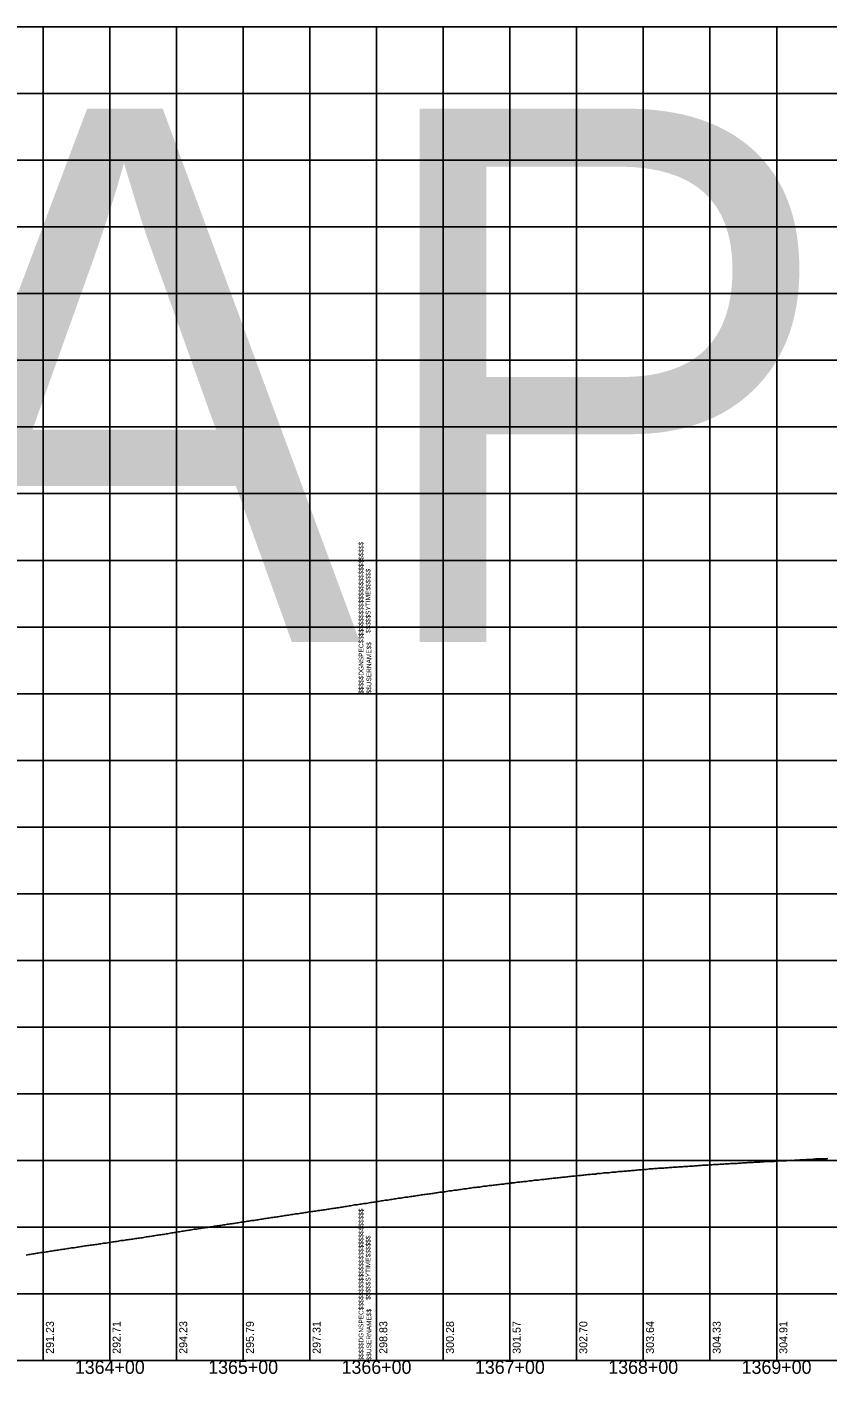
# Model space of a CAD drawing. Extents: x -90830 to 2015517, y -20856 to 836331.
# Drawn here: x 15761 to 16361, y 20053 to 21063 of the extents above; entities that cross this region are included whole.
import ezdxf

# ---------------------------------------------------------------- set-up
doc = ezdxf.new("R2010")
doc.units = 0
for name, color, linetype in [('Level 1', 7, 'Continuous'), ('RD_DDB_Profile_EX', 7, 'Continuous'), ('RD_DDB_StaTX', 7, 'Continuous'), ('RD_DDB_StripGrade', 7, 'Continuous'), ('RD_GPK_Profile_Cell', 7, 'Continuous')]:
    doc.layers.add(name, color=color, linetype=linetype)

msp = doc.modelspace()

# ---------------------------------------------------------------- linework, layer by layer
at = {"layer": 'Level 1'}
for p, q in [((14423.5, 21062.9), (16023.5, 21062.9)), ((15773.5, 21062.9), (15773.5, 20562.9)), ((15823.5, 21062.9), (15823.5, 20562.9)), ((15873.5, 21062.9), (15873.5, 20562.9)), ((15923.5, 21062.9), (15923.5, 20562.9)), ((15973.5, 21062.9), (15973.5, 20562.9)), ((16023.5, 21062.9), (16023.5, 20562.9)), ((16023.5, 21062.9), (16023.5, 20562.9)), ((16023.5, 21062.9), (17623.5, 21062.9)), ((16023.5, 21062.9), (16023.5, 20562.9)), ((16073.5, 21062.9), (16073.5, 20562.9)), ((16123.5, 21062.9), (16123.5, 20562.9)), ((16173.5, 21062.9), (16173.5, 20562.9)), ((16223.5, 21062.9), (16223.5, 20562.9)), ((16273.5, 21062.9), (16273.5, 20562.9)), ((16323.5, 21062.9), (16323.5, 20562.9)), ((14423.5, 21012.9), (16023.5, 21012.9)), ((16023.5, 21012.9), (17623.5, 21012.9)), ((14423.5, 20962.9), (16023.5, 20962.9)), ((16023.5, 20962.9), (17623.5, 20962.9)), ((14423.5, 20912.9), (16023.5, 20912.9)), ((16023.5, 20912.9), (17623.5, 20912.9)), ((14423.5, 20862.9), (16023.5, 20862.9)), ((16023.5, 20862.9), (17623.5, 20862.9)), ((14423.5, 20812.9), (16023.5, 20812.9)), ((16023.5, 20812.9), (17623.5, 20812.9)), ((14423.5, 20762.9), (16023.5, 20762.9)), ((16023.5, 20762.9), (17623.5, 20762.9)), ((14423.5, 20712.9), (16023.5, 20712.9)), ((16023.5, 20712.9), (17623.5, 20712.9)), ((14423.5, 20662.9), (16023.5, 20662.9)), ((16023.5, 20662.9), (17623.5, 20662.9)), ((14423.5, 20612.9), (16023.5, 20612.9)), ((16023.5, 20612.9), (17623.5, 20612.9)), ((14423.5, 20562.9), (16023.5, 20562.9)), ((14423.5, 20562.9), (16023.5, 20562.9)), ((15773.5, 20562.9), (15773.5, 20062.9)), ((15823.5, 20562.9), (15823.5, 20062.9)), ((15873.5, 20562.9), (15873.5, 20062.9)), ((15923.5, 20562.9), (15923.5, 20062.9)), ((15973.5, 20562.9), (15973.5, 20062.9)), ((16023.5, 20562.9), (17623.5, 20562.9)), ((16023.5, 20562.9), (16023.5, 20062.9)), ((16023.5, 20562.9), (16023.5, 20062.9)), ((16023.5, 20562.9), (17623.5, 20562.9)), ((16023.5, 20562.9), (16023.5, 20062.9)), ((16073.5, 20562.9), (16073.5, 20062.9)), ((16123.5, 20562.9), (16123.5, 20062.9)), ((16173.5, 20562.9), (16173.5, 20062.9)), ((16223.5, 20562.9), (16223.5, 20062.9)), ((16273.5, 20562.9), (16273.5, 20062.9)), ((16323.5, 20562.9), (16323.5, 20062.9)), ((14423.5, 20512.9), (16023.5, 20512.9)), ((16023.5, 20512.9), (17623.5, 20512.9)), ((14423.5, 20462.9), (16023.5, 20462.9)), ((16023.5, 20462.9), (17623.5, 20462.9)), ((14423.5, 20412.9), (16023.5, 20412.9)), ((16023.5, 20412.9), (17623.5, 20412.9)), ((14423.5, 20362.9), (16023.5, 20362.9)), ((16023.5, 20362.9), (17623.5, 20362.9)), ((14423.5, 20312.9), (16023.5, 20312.9)), ((16023.5, 20312.9), (17623.5, 20312.9)), ((14423.5, 20262.9), (16023.5, 20262.9)), ((16023.5, 20262.9), (17623.5, 20262.9)), ((14423.5, 20212.9), (16023.5, 20212.9)), ((16023.5, 20212.9), (17623.5, 20212.9)), ((14423.5, 20162.9), (16023.5, 20162.9)), ((16023.5, 20162.9), (17623.5, 20162.9)), ((14423.5, 20112.9), (16023.5, 20112.9)), ((16023.5, 20112.9), (17623.5, 20112.9)), ((14423.5, 20062.9), (16023.5, 20062.9)), ((16023.5, 20062.9), (17623.5, 20062.9))]:
    msp.add_line(p, q, dxfattribs=at)
at = {"layer": 'RD_DDB_Profile_EX'}
for points in [[(16236.8, 20207.1), (16237.8, 20207.2), (16238.8, 20207.2), (16239.8, 20207.3), (16240.8, 20207.4), (16241.8, 20207.4), (16242.8, 20207.6), (16243.8, 20207.5), (16244.8, 20207.7), (16245.8, 20207.8), (16246.8, 20207.8), (16247.8, 20207.9), (16248.8, 20207.9), (16249.8, 20208), (16250.8, 20208.1), (16251.8, 20208.1), (16252.8, 20208.2), (16253.8, 20208.3), (16254.8, 20208.3), (16255.8, 20208.4), (16256.8, 20208.4), (16257.8, 20208.5), (16258.8, 20208.6), (16259.8, 20208.7), (16260.8, 20208.7), (16261.8, 20208.8), (16262.8, 20208.9), (16263.8, 20208.9), (16264.8, 20209), (16265.8, 20209.2), (16266.8, 20209.2), (16267.8, 20209.3), (16268.8, 20209.3), (16269.8, 20209.3), (16270.8, 20209.4), (16271.8, 20209.4), (16272.8, 20209.5), (16273.8, 20209.5), (16274.8, 20209.7), (16275.8, 20209.8), (16276.8, 20209.8), (16277.8, 20209.8), (16278.8, 20209.9), (16279.8, 20209.9), (16280.8, 20210), (16281.8, 20210.1), (16282.8, 20210.1), (16283.8, 20210.1), (16284.8, 20210.3), (16285.8, 20210.3), (16286.8, 20210.3), (16287.8, 20210.4), (16288.8, 20210.5), (16289.8, 20210.6), (16290.8, 20210.6), (16291.8, 20210.7), (16292.8, 20210.7), (16293.8, 20210.7), (16294.8, 20210.8), (16295.8, 20210.9), (16296.8, 20210.9), (16297.8, 20211), (16298.8, 20211.1), (16299.8, 20211.1), (16300.8, 20211.2), (16301.8, 20211.3), (16302.8, 20211.4), (16303.8, 20211.4), (16304.8, 20211.4), (16305.8, 20211.4), (16306.8, 20211.5), (16307.8, 20211.5), (16308.8, 20211.6), (16309.8, 20211.7), (16310.8, 20211.7), (16311.8, 20211.8), (16312.8, 20211.8), (16313.8, 20211.9), (16314.8, 20212), (16315.8, 20212), (16316.8, 20212.1), (16317.8, 20212.2), (16318.8, 20212.2), (16319.8, 20212.2), (16320.8, 20212.2), (16321.8, 20212.2), (16322.8, 20212.3), (16323.8, 20212.5), (16324.8, 20212.5), (16325.8, 20212.5), (16326.8, 20212.6), (16327.8, 20212.6), (16328.8, 20212.6), (16329.8, 20212.7), (16330.8, 20212.7), (16331.8, 20212.9), (16332.8, 20212.9), (16333.8, 20212.9), (16334.8, 20213), (16335.8, 20212.9), (16336.8, 20213)], [(16336.8, 20213), (16337.8, 20213), (16338.8, 20213.1), (16339.8, 20213.2), (16340.8, 20213.3), (16341.8, 20213.4), (16342.8, 20213.4), (16343.8, 20213.4), (16344.8, 20213.4), (16345.8, 20213.5), (16346.8, 20213.6), (16347.8, 20213.6), (16348.8, 20213.6), (16349.8, 20213.7), (16350.8, 20213.8), (16351.8, 20213.8), (16352.8, 20214), (16353.8, 20214), (16354.8, 20214), (16355.8, 20214), (16356.8, 20214), (16357.8, 20214), (16358.8, 20214), (16359.8, 20214.1), (16360.8, 20214.2), (16361.8, 20214.3)], [(16136.8, 20197.4), (16137.8, 20197.5), (16138.8, 20197.6), (16139.8, 20197.7), (16140.8, 20197.9), (16141.8, 20198), (16142.8, 20198.1), (16143.8, 20198.2), (16144.8, 20198.2), (16145.8, 20198.3), (16146.8, 20198.5), (16147.8, 20198.6), (16148.8, 20198.7), (16149.8, 20198.8), (16150.8, 20198.9), (16151.8, 20199), (16152.8, 20199.2), (16153.8, 20199.3), (16154.8, 20199.4), (16155.8, 20199.5), (16156.8, 20199.6), (16157.8, 20199.7), (16158.8, 20199.8), (16159.8, 20199.9), (16160.8, 20200), (16161.8, 20200.2), (16162.8, 20200.3), (16163.8, 20200.3), (16164.8, 20200.4), (16165.8, 20200.6), (16166.8, 20200.7), (16167.8, 20200.9), (16168.8, 20200.9), (16169.8, 20201), (16170.8, 20201.1), (16171.8, 20201.2), (16172.8, 20201.3), (16173.8, 20201.4), (16174.8, 20201.6), (16175.8, 20201.7), (16176.8, 20201.7), (16177.8, 20201.8), (16178.8, 20201.9), (16179.8, 20202), (16180.8, 20202.1), (16181.8, 20202.3), (16182.8, 20202.4), (16183.8, 20202.4), (16184.8, 20202.5), (16185.8, 20202.6), (16186.8, 20202.7), (16187.8, 20202.7), (16188.8, 20203), (16189.8, 20203), (16190.8, 20203.2), (16191.8, 20203.2), (16192.8, 20203.3), (16193.8, 20203.5), (16194.8, 20203.6), (16195.8, 20203.6), (16196.8, 20203.7), (16197.8, 20203.7), (16198.8, 20203.8), (16199.8, 20204), (16200.8, 20204.1), (16201.8, 20204.2), (16202.8, 20204.2), (16203.8, 20204.4), (16204.8, 20204.5), (16205.8, 20204.6), (16206.8, 20204.6), (16207.8, 20204.7), (16208.8, 20204.8), (16209.8, 20204.8), (16210.8, 20204.9), (16211.8, 20205.1), (16212.8, 20205.2), (16213.8, 20205.2), (16214.8, 20205.4), (16215.8, 20205.4), (16216.8, 20205.4), (16217.8, 20205.6), (16218.8, 20205.7), (16219.8, 20205.8), (16220.8, 20205.9), (16221.8, 20205.9), (16222.8, 20206), (16223.8, 20206.1), (16224.8, 20206.2), (16225.8, 20206.2), (16226.8, 20206.3), (16227.8, 20206.5), (16228.8, 20206.5), (16229.8, 20206.6), (16230.8, 20206.6), (16231.8, 20206.8), (16232.8, 20206.8), (16233.8, 20206.9), (16234.8, 20207), (16235.8, 20207.1), (16236.8, 20207.1)], [(16036.8, 20184), (16037.8, 20184.1), (16038.8, 20184.3), (16039.8, 20184.5), (16040.8, 20184.6), (16041.8, 20184.7), (16042.8, 20184.9), (16043.8, 20185.1), (16044.8, 20185.3), (16045.8, 20185.3), (16046.8, 20185.4), (16047.8, 20185.6), (16048.8, 20185.8), (16049.8, 20185.9), (16050.8, 20186.1), (16051.8, 20186.2), (16052.8, 20186.4), (16053.8, 20186.5), (16054.8, 20186.7), (16055.8, 20186.8), (16056.8, 20187), (16057.8, 20187.2), (16058.8, 20187.3), (16059.8, 20187.4), (16060.8, 20187.5), (16061.8, 20187.6), (16062.8, 20187.8), (16063.8, 20187.9), (16064.8, 20188.1), (16065.8, 20188.2), (16066.8, 20188.4), (16067.8, 20188.5), (16068.8, 20188.7), (16069.8, 20188.9), (16070.8, 20189), (16071.8, 20189.1), (16072.8, 20189.2), (16073.8, 20189.3), (16074.8, 20189.4), (16075.8, 20189.7), (16076.8, 20189.8), (16077.8, 20190), (16078.8, 20190.1), (16079.8, 20190.1), (16080.8, 20190.4), (16081.8, 20190.5), (16082.8, 20190.6), (16083.8, 20190.6), (16084.8, 20190.9), (16085.8, 20191.1), (16086.8, 20191.2), (16087.8, 20191.4), (16088.8, 20191.6), (16089.8, 20191.7), (16090.8, 20191.7), (16091.8, 20191.8), (16092.8, 20192.1), (16093.8, 20192.2), (16094.8, 20192.3), (16095.8, 20192.5), (16096.8, 20192.6), (16097.8, 20192.7), (16098.8, 20192.9), (16099.8, 20192.9), (16100.8, 20192.9), (16101.8, 20193.2), (16102.8, 20193.4), (16103.8, 20193.5), (16104.8, 20193.6), (16105.8, 20193.7), (16106.8, 20193.8), (16107.8, 20194), (16108.8, 20194.1), (16109.8, 20194.2), (16110.8, 20194.3), (16111.8, 20194.4), (16112.8, 20194.6), (16113.8, 20194.7), (16114.8, 20194.8), (16115.8, 20194.9), (16116.8, 20195), (16117.8, 20195), (16118.8, 20195.1), (16119.8, 20195.4), (16120.8, 20195.5), (16121.8, 20195.5), (16122.8, 20195.6), (16123.8, 20195.7), (16124.8, 20196), (16125.8, 20196), (16126.8, 20196.1), (16127.8, 20196.3), (16128.8, 20196.5), (16129.8, 20196.5), (16130.8, 20196.5), (16131.8, 20196.8), (16132.8, 20196.9), (16133.8, 20197), (16134.8, 20197.1), (16135.8, 20197.2), (16136.8, 20197.4)], [(15936.8, 20168.8), (15937.8, 20169), (15938.8, 20169.1), (15939.8, 20169.3), (15940.8, 20169.5), (15941.8, 20169.6), (15942.8, 20169.7), (15943.8, 20169.9), (15944.8, 20170.1), (15945.8, 20170.2), (15946.8, 20170.3), (15947.8, 20170.5), (15948.8, 20170.6), (15949.8, 20170.7), (15950.8, 20171), (15951.8, 20171.2), (15952.8, 20171.2), (15953.8, 20171.4), (15954.8, 20171.6), (15955.8, 20171.7), (15956.8, 20171.9), (15957.8, 20172), (15958.8, 20172.2), (15959.8, 20172.3), (15960.8, 20172.5), (15961.8, 20172.7), (15962.8, 20172.8), (15963.8, 20172.9), (15964.8, 20173), (15965.8, 20173.2), (15966.8, 20173.3), (15967.8, 20173.5), (15968.8, 20173.6), (15969.8, 20173.8), (15970.8, 20174), (15971.8, 20174.1), (15972.8, 20174.3), (15973.8, 20174.5), (15974.8, 20174.6), (15975.8, 20174.7), (15976.8, 20174.9), (15977.8, 20175), (15978.8, 20175.2), (15979.8, 20175.4), (15980.8, 20175.4), (15981.8, 20175.6), (15982.8, 20175.7), (15983.8, 20175.9), (15984.8, 20176), (15985.8, 20176.2), (15986.8, 20176.3), (15987.8, 20176.5), (15988.8, 20176.6), (15989.8, 20176.8), (15990.8, 20176.9), (15991.8, 20177.1), (15992.8, 20177.2), (15993.8, 20177.4), (15994.8, 20177.5), (15995.8, 20177.7), (15996.8, 20177.9), (15997.8, 20178), (15998.8, 20178.2), (15999.8, 20178.3), (16000.8, 20178.5), (16001.8, 20178.6), (16002.8, 20178.8), (16003.8, 20178.9), (16004.8, 20179.1), (16005.8, 20179.3), (16006.8, 20179.5), (16007.8, 20179.6), (16008.8, 20179.7), (16009.8, 20179.9), (16010.8, 20180.1), (16011.8, 20180.2), (16012.8, 20180.3), (16013.8, 20180.5), (16014.8, 20180.7), (16015.8, 20180.7), (16016.8, 20180.9), (16017.8, 20181.1), (16018.8, 20181.3), (16019.8, 20181.4), (16020.8, 20181.5), (16021.8, 20181.6), (16022.8, 20181.9), (16023.8, 20182.1), (16024.8, 20182.2), (16025.8, 20182.3), (16026.8, 20182.5), (16027.8, 20182.6), (16028.8, 20182.8), (16029.8, 20183), (16030.8, 20183.1), (16031.8, 20183.1), (16032.8, 20183.3), (16033.8, 20183.5), (16034.8, 20183.7), (16035.8, 20183.8), (16036.8, 20184)], [(15836.8, 20153.5), (15837.8, 20153.6), (15838.8, 20153.7), (15839.8, 20153.8), (15840.8, 20154), (15841.8, 20154.2), (15842.8, 20154.3), (15843.8, 20154.5), (15844.8, 20154.6), (15845.8, 20154.7), (15846.8, 20154.9), (15847.8, 20155), (15848.8, 20155.1), (15849.8, 20155.4), (15850.8, 20155.6), (15851.8, 20155.7), (15852.8, 20155.9), (15853.8, 20156), (15854.8, 20156.1), (15855.8, 20156.3), (15856.8, 20156.4), (15857.8, 20156.6), (15858.8, 20156.8), (15859.8, 20157), (15860.8, 20157.1), (15861.8, 20157.2), (15862.8, 20157.4), (15863.8, 20157.5), (15864.8, 20157.7), (15865.8, 20157.9), (15866.8, 20158), (15867.8, 20158.2), (15868.8, 20158.4), (15869.8, 20158.6), (15870.8, 20158.7), (15871.8, 20158.8), (15872.8, 20158.9), (15873.8, 20159.1), (15874.8, 20159.3), (15875.8, 20159.5), (15876.8, 20159.7), (15877.8, 20159.9), (15878.8, 20160), (15879.8, 20160.1), (15880.8, 20160.3), (15881.8, 20160.4), (15882.8, 20160.6), (15883.8, 20160.7), (15884.8, 20160.9), (15885.8, 20161.1), (15886.8, 20161.3), (15887.8, 20161.4), (15888.8, 20161.5), (15889.8, 20161.7), (15890.8, 20161.8), (15891.8, 20162), (15892.8, 20162.2), (15893.8, 20162.3), (15894.8, 20162.5), (15895.8, 20162.6), (15896.8, 20162.6), (15897.8, 20162.9), (15898.8, 20163.1), (15899.8, 20163.2), (15900.8, 20163.4), (15901.8, 20163.6), (15902.8, 20163.7), (15903.8, 20163.8), (15904.8, 20164), (15905.8, 20164.1), (15906.8, 20164.2), (15907.8, 20164.5), (15908.8, 20164.6), (15909.8, 20164.7), (15910.8, 20164.9), (15911.8, 20165.1), (15912.8, 20165.2), (15913.8, 20165.4), (15914.8, 20165.5), (15915.8, 20165.7), (15916.8, 20165.7), (15917.8, 20165.9), (15918.8, 20166.1), (15919.8, 20166.2), (15920.8, 20166.4), (15921.8, 20166.6), (15922.8, 20166.7), (15923.8, 20166.9), (15924.8, 20167), (15925.8, 20167.1), (15926.8, 20167.3), (15927.8, 20167.5), (15928.8, 20167.6), (15929.8, 20167.8), (15930.8, 20167.8), (15931.8, 20168), (15932.8, 20168.2), (15933.8, 20168.3), (15934.8, 20168.5), (15935.8, 20168.7), (15936.8, 20168.8)], [(15760.8, 20142), (15761.8, 20142.2), (15762.8, 20142.4), (15763.8, 20142.5), (15764.8, 20142.7), (15765.8, 20142.8), (15766.8, 20143), (15767.8, 20143.1), (15768.8, 20143.3), (15769.8, 20143.4), (15770.8, 20143.6), (15771.8, 20143.8), (15772.8, 20143.9), (15773.8, 20144), (15774.8, 20144.2), (15775.8, 20144.3), (15776.8, 20144.5), (15777.8, 20144.7), (15778.8, 20144.8), (15779.8, 20145), (15780.8, 20145.1), (15781.8, 20145.3), (15782.8, 20145.4), (15783.8, 20145.6), (15784.8, 20145.7), (15785.8, 20145.9), (15786.8, 20146.1), (15787.8, 20146.2), (15788.8, 20146.3), (15789.8, 20146.5), (15790.8, 20146.7), (15791.8, 20146.8), (15792.8, 20146.9), (15793.8, 20147.1), (15794.8, 20147.3), (15795.8, 20147.4), (15796.8, 20147.5), (15797.8, 20147.6), (15798.8, 20147.8), (15799.8, 20148), (15800.8, 20148.2), (15801.8, 20148.3), (15802.8, 20148.5), (15803.8, 20148.7), (15804.8, 20148.8), (15805.8, 20149), (15806.8, 20149.1), (15807.8, 20149.2), (15808.8, 20149.3), (15809.8, 20149.4), (15810.8, 20149.6), (15811.8, 20149.7), (15812.8, 20149.9), (15813.8, 20150), (15814.8, 20150.1), (15815.8, 20150.3), (15816.8, 20150.4), (15817.8, 20150.6), (15818.8, 20150.8), (15819.8, 20150.8), (15820.8, 20150.9), (15821.8, 20151.1), (15822.8, 20151.3), (15823.8, 20151.5), (15824.8, 20151.7), (15825.8, 20151.8), (15826.8, 20151.9), (15827.8, 20152.1), (15828.8, 20152.2), (15829.8, 20152.3), (15830.8, 20152.6), (15831.8, 20152.8), (15832.8, 20152.9), (15833.8, 20153), (15834.8, 20153.1), (15835.8, 20153.3), (15836.8, 20153.5)]]:
    msp.add_lwpolyline(points, dxfattribs=at)
at = {"layer": 'RD_GPK_Profile_Cell'}
msp.add_line((14436.8, 20062.9), (16636.8, 20062.9), dxfattribs=at)

# ---------------------------------------------------------------- texts
at = {"layer": 'Level 1'}
for s, p in [('$$$$$DGNSPEC$$$$$$$$$$$$$$$$$$$$$$$$$$$$', (16013.6, 20562.8)), ('$$$$$SYTIME$$$$$$', (16018.9, 20608.4)), ('$$USERNAME$$', (16019.5, 20563)), ('$$$$$DGNSPEC$$$$$$$$$$$$$$$$$$$$$$$$$$$$', (16013.6, 20062.8)), ('$$$$$SYTIME$$$$$$', (16018.9, 20108.4)), ('$$USERNAME$$', (16019.5, 20063))]:
    msp.add_text(s, height=3.544, rotation=90, dxfattribs=at).set_placement(p)
at = {"layer": 'RD_DDB_StaTX'}
for s, p in [('1364+00', (15797.2, 20052.9)), ('1365+00', (15897.2, 20052.9)), ('1366+00', (15997.2, 20052.9)), ('1367+00', (16097.2, 20052.9)), ('1368+00', (16197.2, 20052.9)), ('1369+00', (16297.2, 20052.9))]:
    msp.add_text(s, height=10, dxfattribs=at).set_placement(p)
at = {"layer": 'RD_DDB_StripGrade'}
for s, p in [('291.23', (15781.5, 20067.9)), ('292.71', (15831.5, 20067.9)), ('294.23', (15881.5, 20067.9)), ('295.79', (15931.5, 20067.9)), ('297.31', (15981.5, 20067.9)), ('298.83', (16031.5, 20067.9)), ('300.28', (16081.5, 20067.9)), ('301.57', (16131.5, 20067.9)), ('302.70', (16181.5, 20067.9)), ('303.64', (16231.5, 20067.9)), ('304.33', (16281.5, 20067.9)), ('304.91', (16331.5, 20067.9))]:
    msp.add_text(s, height=6, rotation=90, dxfattribs=at).set_placement(p)
at = {"layer": 'RD_GPK_Profile_Cell'}
msp.add_text('NOGAP', height=400, dxfattribs=at).set_placement((14436.8, 20601.6))

doc.saveas('drawing.dxf')
